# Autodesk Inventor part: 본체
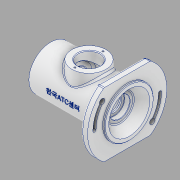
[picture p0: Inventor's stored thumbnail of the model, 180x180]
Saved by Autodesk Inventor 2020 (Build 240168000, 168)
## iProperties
Created: 2022-05
Part Number: 본체
Material: 알루미늄 6061
Document SubType Name: Modeling
Designer: Student
Density: 2.7 g/cm^3
Appearance: 알루미늄 - 평지
Mass: 691.495 g
Surface Area: 623.5 cm^2
Volume: 256.109 cm^3
Author: Student
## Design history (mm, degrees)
sketch "스케치2"
  geometry: L1 (47, 33.985)-(47, -33.985); L2 (-47, 33.985)-(-47, -33.985); A1 r 58 centre (0, 0) between (47, 33.985) and (-47, 33.985); A2 r 58 centre (0, 0) between (-47, -33.985) and (47, -33.985); 5 further points
  constraints: 6 point on circle, 4 end point, 2 centre point, 2 horizontal alignment, 2 midpoint, 2 vertical, 2 vertical alignment, 1 coincident
  dimensions: "d0" = 58 radius of A1; "d1" = 94 distance between parallel lines of L2 L1
extrude "돌출1" new body sketch "스케치2" distance "d2" = 10; taper "d3" = 0 deg
sketch "스케치3"
  geometry: C1 r 36 at (0, 0); 1 further point
  constraints: 1 centre point, 1 coincident
  dimensions: "d4" = 72 diameter of C1
extrude "돌출2" join sketch "스케치3" distance "d5" = 3; taper "d6" = 0 deg
sketch "스케치4"
  geometry: C1 r 32 at (0, 0); 1 further point
  constraints: 1 centre point, 1 coincident
  dimensions: "d7" = 64 diameter of C1
extrude "돌출3" join sketch "스케치4" distance "d8" = 102; taper "d9" = 0 deg
sketch "스케치5"
  geometry: L1 (13, -36)-(13, 36) reference; L2 (-9, 11)-(-11, 11); L3 (-11, 11)-(-11, 15); L4 (-11, 15)-(-16, 15); L5 (-16, 15)-(-16, 17.5); L6 (-16, 17.5)-(-27, 17.5); L7 (-27, 17.5)-(-27, 27); L8 (-27, 27)-(-65, 27); L9 (10, -47)-(10, 47) reference; L10 (-133.779, 0)-(159.779, 0); L11 (13, 30)-(13, 0); L12 (13, 30)-(-1, 20); L13 (-1, 20)-(-1, 15.404); L14 (0, -47)-(0, 47) reference; L15 (-9, 11)-(-9, 15); L16 (-9, 15)-(-1.7, 15); L17 (-1.7, 15)-(-1, 15.404); L18 (-102, 32)-(-102, -32) reference; L19 (-65, 27)-(-65, 17.5); L20 (-65, 17.5)-(-76, 17.5); L21 (-76, 17.5)-(-76, 18.5); L22 (-76, 18.5)-(-77.75, 18.5); L23 (-77.75, 18.5)-(-77.75, 17.5); L24 (-77.75, 17.5)-(-80, 17.5); L25 (-80, 17.5)-(-80, 22.5); L26 (-80, 22.5)-(-91, 22.5); L27 (-91, 22.5)-(-91, 24); L28 (-91, 24)-(-94, 24); L29 (-94, 24)-(-94, 0); L30 (13, 0)-(-94, 0); 2 further points
  constraints: 52 end point, 13 perpendicular, 5 horizontal, 3 vertical, 2 midpoint, 2 point on line, 1 coincident, 1 collinear, 1 parallel
  dimensions: "d10" = 60 diameter of L11.start L10; "d11" = 40 diameter of L12.end L10; "d12" = 22 diameter of L2 L10; "d13" = 14 distance between parallel lines of L1 L13; "d14" = 30 deg angle of L16 L17; "d15" = 0.7 horizontal distance of L13.end L16.end; "d16" = 7.3 distance of L15.end L16.end; "d17" = 30 diameter of L16 L10; "d18" = 5 distance of L3.end L4.end; "d19" = 29 distance from line of L1 L4.end; "d20" = 54 diameter of L8 L10; "d21" = 30 diameter of L4 L10; "d22" = 35 diameter of L6 L10; "d23" = 11 distance of L5.end L6.end; "d24" = 38 distance of L7.end L8.end; "d47" = 35 diameter of L20 L10; "d48" = 11 distance of L19.end L20.end; "d51" = 1.75 distance of L21.end L22.end; "d52" = 37 diameter of L22 L10; "d53" = 4 horizontal distance of L21.end L24.end; "d54" = 35 diameter of L24 L10; "d55" = 45 diameter of L26 L10; "d56" = 48 diameter of L28 L10; "d58" = 8 distance between parallel lines of L18 L29; "d59" = 3 distance of L27.end L28.end; "d156" = 146.77878 distance from line of L10.end L1
revolve "회전1" sketch "스케치5" stored, may be unused: angle "d60" = 90 deg
sketch "스케치6"
  geometry: 2 further points
  constraints: 1 coincident
hole "구멍1" sketch "스케치6" at (0, 0) diameter "d61" = 43.376; stored, may be unused: countersink angle "d65" = 90 deg, drill point angle "d67" = 0 deg; dims "d62" = 8, "d63" = 4, "d64" = 2, "d66" = 10
chamfer "모따기1" distance "d68" = 1; stored, may be unused: second distance "d69" = 2, angle "d70" = 45 deg
chamfer "모따기2" distance "d71" = 1; stored, may be unused: second distance "d72" = 2, angle "d73" = 45 deg
chamfer "모따기3" distance "d74" = 1; stored, may be unused: second distance "d75" = 2, angle "d76" = 45 deg
fillet "모깎기1" dims "d77" = 3
fillet "모깎기2" dims "d78" = 0.5
fillet "모깎기3" dims "d79" = 0.6
sketch "스케치10"
  geometry: L1 (0, 0)-(-36.77, 30.854); L2 (-61.812, 0)-(67.211, 0); L3 (36.77, -30.854)-(0, 0); A1 r 48 centre (0, 0) between (-36.77, 30.854) and (36.77, -30.854); A2 r 48 centre (0, 0) between (-36.77, 30.854) and (-48, 0); A3 r 50.25 centre (0, 0) between (-38.494, 32.3) and (-50.25, 0); A4 r 45.75 centre (0, 0) between (-35.047, 29.408) and (-45.75, 0); A5 r 2.25 centre (-36.77, 30.854) between (-35.047, 29.408) and (-38.494, 32.3); A6 r 2.25 centre (-48, 0) between (-50.25, 0) and (-45.75, 0); A7 r 48 centre (0, 0) between (36.77, -30.854) and (48, 0); A8 r 50.25 centre (0, 0) between (38.494, -32.3) and (50.25, 0); A9 r 45.75 centre (0, 0) between (35.047, -29.408) and (45.75, 0); A10 r 2.25 centre (36.77, -30.854) between (35.047, -29.408) and (38.494, -32.3); A11 r 2.25 centre (48, 0) between (50.25, 0) and (45.75, 0); 1 further point
  constraints: 22 point on circle, 11 centre point, 8 tangent, 6 end point, 3 coincident, 2 horizontal alignment, 1 concentric, 1 horizontal
  dimensions: "d99" = 96 diameter of A1; "d100" = 4.5 diameter of A6; "d101" = 40 deg angle of L2 L1; "d102" = 4.5 diameter of A11; "d103" = 40 deg angle of L3 L2
extrude "돌출6" cut sketch "스케치10" distance "d104" = 5.6; taper "d105" = 0 deg
sketch "스케치11"
  geometry: A1 r 2.25 centre (-36.77, 30.854) between (-35.047, 29.408) and (-38.494, 32.3) reference; A2 r 50.25 centre (0, 0) between (-38.494, 32.3) and (-50.25, 0) reference; A3 r 2.25 centre (-48, 0) between (-50.25, 0) and (-45.75, 0) reference; A4 r 45.75 centre (0, 0) between (-35.047, 29.408) and (-45.75, 0) reference; A5 r 50.25 centre (0, 0) between (38.494, -32.3) and (50.25, 0) reference; A6 r 2.25 centre (48, 0) between (50.25, 0) and (45.75, 0) reference; A7 r 45.75 centre (0, 0) between (35.047, -29.408) and (45.75, 0) reference; A8 r 2.25 centre (36.77, -30.854) between (35.047, -29.408) and (38.494, -32.3) reference; A9 r 48 centre (0, 0) between (-36.77, 30.854) and (-48, 0); A10 r 52 centre (0, 0) between (-39.834, 33.425) and (-52, 0); A11 r 44 centre (0, 0) between (-33.706, 28.283) and (-44, 0); A12 r 4 centre (-36.77, 30.854) between (-33.706, 28.283) and (-39.834, 33.425); A13 r 4 centre (-48, 0) between (-52, 0) and (-44, 0); A14 r 48 centre (0, 0) between (36.77, -30.854) and (48, 0); A15 r 52 centre (0, 0) between (39.834, -33.425) and (52, 0); A16 r 44 centre (0, 0) between (33.706, -28.283) and (44, 0); A17 r 4 centre (36.77, -30.854) between (33.706, -28.283) and (39.834, -33.425); A18 r 4 centre (48, 0) between (52, 0) and (44, 0); 1 further point
  constraints: 20 point on circle, 10 centre point, 8 tangent, 2 coincident, 1 concentric
  dimensions: "d106" = 8 diameter of A12; "d107" = 8 diameter of A17 (derived)
extrude "돌출7" cut sketch "스케치11" distance "d108" = 4.4; taper "d109" = 0 deg
sketch "스케치12"
  geometry: A1 r 2.25 centre (-36.77, 30.854) between (-35.047, 29.408) and (-38.494, 32.3) reference; A2 r 2.25 centre (48, 0) between (50.25, 0) and (45.75, 0) reference; A3 r 2.25 centre (36.77, -30.854) between (35.047, -29.408) and (38.494, -32.3) reference; 1 further point
hole "구멍3" sketch "스케치12" at (-36.77, 30.854), (36.77, -30.854) diameter "d110" = 8; stored, may be unused: countersink angle "d114" = 90 deg, drill point angle "d116" = 0 deg; dims "d111" = 8, "d112" = 4, "d113" = 2, "d115" = 10
node "작업 평면1"
sketch "스케치13"
  geometry: L1 (102, -32)-(102, 32) reference; L2 (-10, -33.985)-(-10, 33.985) reference; C1 r 25 at (46, 0); 2 further points
  constraints: 1 centre point, 1 horizontal alignment, 1 midpoint
  dimensions: "d118" = 50 diameter of C1; "d119" = 56 distance from line of L1 C1.centre
extrude "돌출8" join sketch "스케치13" stored distance "d120" = 4.4; taper "d121" = 5 deg
sketch "스케치14"
  geometry: C1 r 25 at (0, 0) reference; 1 further point
hole "구멍4" sketch "스케치14" at (0, 0) diameter "d122" = 32; stored, may be unused: countersink angle "d126" = 90 deg, drill point angle "d128" = 0 deg; dims "d123" = 8, "d124" = 4, "d125" = 2, "d127" = 35
sketch "스케치15"
  geometry: A1 r 20.5 centre (0, 0) between (0, 20.5) and (0, -20.5); 1 further point
  constraints: 2 point on circle, 1 centre point, 1 vertical alignment
  dimensions: "d129" = 41 diameter of A1; "d130" = 50.3612 distance of point (46, 0) A1.start; "d131" = 46 distance of point (46, 0) A1.centre; "d132" = 50.3612 distance of point (46, 0) A1.end
hole "구멍5" sketch "스케치15" at (0, 20.5), (0, -20.5) diameter "d133" = 2.459; stored, may be unused: countersink angle "d137" = 90 deg, drill point angle "d139" = 118 deg; dims "d134" = 6, "d135" = 4, "d136" = 2, "d138" = 8
node "작업 평면2"
sketch "스케치16"
  geometry: L1 (-80.339, 10.962)-(-23.661, 10.962); L2 (-23.661, 10.962)-(-23.661, -10.962); L3 (-23.661, -10.962)-(-80.339, -10.962); L4 (-80.339, -10.962)-(-80.339, 10.962); L5 (-23.661, 0)-(-80.339, 0); L6 (-52, 10.962)-(-52, -10.962); L7 (10, -47)-(10, 47) reference; L8 (10, 0)-(4.4, 0) reference; 3 further points
  constraints: 6 midpoint, 4 end point, 1 horizontal alignment, 2 other
  dimensions: "d141" = 62 distance between parallel lines of L7 L6
feature "엠보싱1" sketch "스케치16" dims "d0" = 58, "d1" = 94, "d142" = 0.5, "d143" = 0
chamfer "모따기4" distance "d144" = 1; stored, may be unused: second distance "d145" = 2, angle "d146" = 45 deg
fillet "모깎기4" dims "d147" = 3
fillet "모깎기5" dims "d148" = 3
fillet "모깎기6" dims "d149" = 3
chamfer "모따기5" distance "d150" = 1; stored, may be unused: second distance "d151" = 2, angle "d152" = 45 deg
chamfer "모따기6" distance "d153" = 1; stored, may be unused: second distance "d154" = 2, angle "d155" = 45 deg
node "솔리드1"
node "투영된 루프2"
node "투영된 루프3"
feature "A9D066F2-1C7D-4E18-AEED-F7BC21143FA4" dims "d61" = 43.376, "d62" = 8, "d63" = 4, "d64" = 2, "d65" = 90 deg, "d66" = 10, "d67" = 0
other parameters: "d117" = 38
